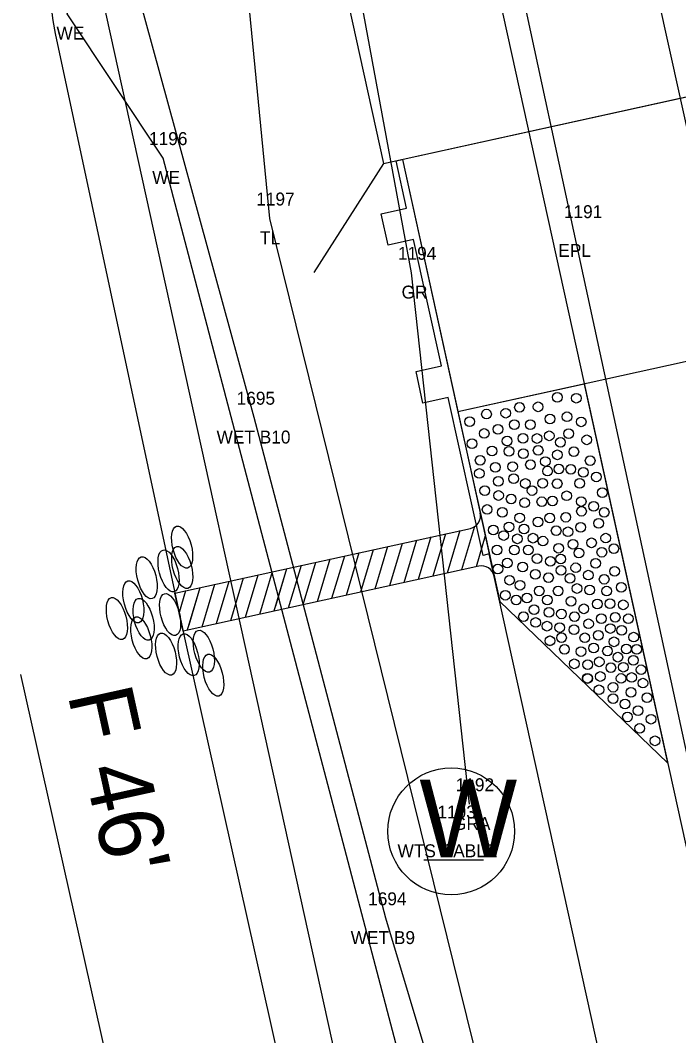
# Model space of a CAD drawing. Extents: x 2520975 to 2526538, y 881018 to 888064.
# Drawn here: x 2523752.6 to 2523803.6, y 884983.7 to 885062.2 of the extents above; entities that cross this region are included whole.
import ezdxf

# ---------------------------------------------------------------- set-up
doc = ezdxf.new("R2010")
doc.units = 0
for name, color, linetype in [('RD_EV_JurisArea', 7, 'Continuous'), ('RD_EX_GuardRail', 7, 'Continuous'), ('RD_EX_GuardRail_txCode', 7, 'Continuous'), ('RD_EX_H2O', 7, 'Continuous'), ('RD_EX_H2O_txCode', 7, 'Continuous'), ('RD_EX_H2O_WetLd_txCode', 7, 'Continuous'), ('RD_EX_Road', 7, 'Continuous'), ('RD_EX_Road_txCode', 7, 'Continuous'), ('RD_EX_UT', 7, 'Continuous'), ('RD_EX_UT_txCode', 7, 'Continuous'), ('RD_EX_VEG', 7, 'Continuous'), ('RD_EX_VEG_txCode', 7, 'Continuous'), ('RD_HC_Cl', 7, 'Continuous'), ('RD_PD_Bridge', 7, 'Continuous'), ('RD_PD_CstnLmt', 7, 'Continuous'), ('RD_PD_DR_ErosCtrl', 7, 'Continuous'), ('RD_PD_Final_TrvlWay', 7, 'Continuous'), ('RD_PD_GR', 7, 'Continuous'), ('RD_PD_PaveShd', 7, 'Continuous'), ('RD_SMD_Locator', 7, 'Continuous')]:
    doc.layers.add(name, color=color, linetype=linetype)

# ---------------------------------------------------------------- blocks, each defined once
blk = doc.blocks.new('TBC1')
at = {"layer": 'RD_PD_GR'}
blk.add_lwpolyline([(12.5, 2.5), (15, 2.5), (15, 0.492), (25, 0.492), (25, 2.5), (27.5, 2.5), (27.5, 0.492), (31.25, 0.492), (31.25, 0), (0, 0), (0, 0.492), (12.5, 0.492)], close=True, dxfattribs=at)

msp = doc.modelspace()

# ---------------------------------------------------------------- linework, layer by layer
at = {"layer": 'RD_EV_JurisArea'}
msp.add_lwpolyline([(2523827.748, 884469.643), (2523867.429, 884517.673), (2523885.95, 884534.838), (2523882.771, 884582.718), (2523847.739, 884736.424), (2523822.93, 884833.786), (2523804.257, 884914.891), (2523780.91, 884992.763), (2523770.735, 885031.476), (2523760.496, 885068.896)], dxfattribs=at)
at = {"layer": 'RD_EX_GuardRail'}
msp.add_lwpolyline([(2523787.377, 885001.584), (2523782.908, 885042.685), (2523776.151, 885079.302)], dxfattribs=at)
at = {"layer": 'RD_EX_H2O'}
msp.add_lwpolyline([(2523792.732, 884941.121), (2523763.674, 885051.555), (2523756.264, 885062.719), (2523770.471, 885094.548), (2523817.567, 885105.706), (2523827.825, 885105.996)], dxfattribs=at)
at = {"layer": 'RD_EX_Road'}
for p, q in [((2523795.465, 885045.906), (2523788.047, 885080.306)), ((2523816.996, 884946.299), (2523795.465, 885045.906))]:
    msp.add_line(p, q, dxfattribs=at)
at = {"layer": 'RD_EX_UT'}
msp.add_line((2523783.84, 884997.269), (2523788.469, 884997.269), dxfattribs=at)
msp.add_circle((2523785.968, 884999.477), 4.908, dxfattribs=at)
at = {"layer": 'RD_EX_VEG'}
msp.add_lwpolyline([(2523800.231, 884418.22), (2523892.245, 884498.974), (2523844.575, 884752.813), (2523771.945, 885046.883), (2523769.056, 885076.621)], dxfattribs=at)
at = {"layer": 'RD_HC_Cl'}
msp.add_line((2523641.165, 885794.201), (2524197.759, 883266.557), dxfattribs=at)
at = {"layer": 'RD_PD_Bridge'}
for p, q in [((2523780.729, 885051.128), (2523826.629, 885061.235)), ((2523780.729, 885051.128), (2523775.344, 885042.702)), ((2523782.194, 885051.45), (2523786.495, 885031.918)), ((2523829.465, 885041.381), (2523786.495, 885031.918))]:
    msp.add_line(p, q, dxfattribs=at)
for points in [[(2523752.772, 885178.086), (2523780.729, 885051.128)], [(2523780.729, 885051.128), (2523826.629, 885061.235)]]:
    msp.add_lwpolyline(points, dxfattribs=at)
at = {"layer": 'RD_PD_CstnLmt'}
for p, q in [((2523755.336, 885061.182), (2523765.326, 885014.455)), ((2523765.326, 885014.455), (2523787.173, 884916.87))]:
    msp.add_line(p, q, dxfattribs=at)
msp.add_arc((2523774.894, 885065.364), 20, 102.41848, 192.06773, dxfattribs=at)
at = {"layer": 'RD_PD_DR_ErosCtrl'}
msp.add_line((2523752.64, 885011.615), (2523774.487, 884914.03), dxfattribs=at)
msp.add_arc((2523774.894, 885065.364), 33, 102.41848, 192.06773, dxfattribs=at)
at = {"layer": 'RD_PD_Final_TrvlWay'}
for p, q in [((2523636.679, 885619.273), (2523984.702, 884038.805)), ((2523696.801, 885485.745), (2524014, 884045.256))]:
    msp.add_line(p, q, dxfattribs=at)
at = {"layer": 'RD_PD_GR'}
msp.add_line((2523896.44, 884532.63), (2523788.914, 885020.932), dxfattribs=at)
at = {"layer": 'RD_PD_PaveShd'}
for p, q in [((2523796.261, 885034.069), (2523786.495, 885031.918)), ((2523796.261, 885034.069), (2523802.712, 885004.771)), ((2523786.495, 885031.918), (2523788.43, 885023.129)), ((2523764.591, 885017.892), (2523787.453, 885022.914)), ((2523786.64, 885022.736), (2523785.656, 885019.448)), ((2523786.64, 885022.736), (2523785.656, 885019.448)), ((2523787.777, 885023.049), (2523786.773, 885019.693)), ((2523788.43, 885023.129), (2523789.076, 885020.199)), ((2523783.288, 885021.999), (2523782.304, 885018.712)), ((2523784.405, 885022.245), (2523783.421, 885018.957)), ((2523784.405, 885022.245), (2523783.421, 885018.957)), ((2523785.523, 885022.49), (2523784.539, 885019.203)), ((2523785.523, 885022.49), (2523784.539, 885019.203)), ((2523788.606, 885022.33), (2523787.89, 885019.939)), ((2523779.936, 885021.263), (2523778.952, 885017.975)), ((2523779.936, 885021.263), (2523778.952, 885017.975)), ((2523781.053, 885021.509), (2523780.069, 885018.221)), ((2523781.053, 885021.509), (2523780.069, 885018.221)), ((2523782.171, 885021.754), (2523781.187, 885018.466)), ((2523782.171, 885021.754), (2523781.187, 885018.466)), ((2523776.584, 885020.527), (2523775.6, 885017.239)), ((2523776.584, 885020.527), (2523775.6, 885017.239)), ((2523777.702, 885020.772), (2523776.718, 885017.485)), ((2523777.702, 885020.772), (2523776.718, 885017.485)), ((2523778.819, 885021.018), (2523777.835, 885017.73)), ((2523778.819, 885021.018), (2523777.835, 885017.73)), ((2523788.099, 885019.985), (2523765.218, 885014.959)), ((2523772.115, 885019.545), (2523771.131, 885016.258)), ((2523772.115, 885019.545), (2523771.131, 885016.258)), ((2523773.233, 885019.791), (2523772.249, 885016.503)), ((2523773.233, 885019.791), (2523772.37, 885016.908)), ((2523774.35, 885020.036), (2523773.366, 885016.748)), ((2523774.35, 885020.036), (2523773.366, 885016.748)), ((2523775.467, 885020.281), (2523774.483, 885016.994)), ((2523775.467, 885020.281), (2523774.483, 885016.994)), ((2523789.076, 885020.199), (2523789.721, 885017.269)), ((2523768.763, 885018.809), (2523767.779, 885015.521)), ((2523768.763, 885018.809), (2523767.779, 885015.521)), ((2523769.881, 885019.054), (2523768.897, 885015.767)), ((2523769.881, 885019.054), (2523768.897, 885015.767)), ((2523770.998, 885019.3), (2523770.014, 885016.012)), ((2523770.998, 885019.3), (2523770.014, 885016.012)), ((2523765.412, 885018.073), (2523764.91, 885016.398)), ((2523766.529, 885018.318), (2523765.545, 885015.03)), ((2523766.529, 885018.318), (2523765.666, 885015.436)), ((2523767.646, 885018.564), (2523766.662, 885015.276)), ((2523767.646, 885018.564), (2523766.662, 885015.276)), ((2523765.218, 885014.959), (2523764.591, 885017.892)), ((2523802.712, 885004.771), (2523789.721, 885017.269))]:
    msp.add_line(p, q, dxfattribs=at)
for centre in [(2523794.177, 885033.047), (2523794.177, 885033.047), (2523795.645, 885032.98), (2523795.645, 885032.98), (2523788.701, 885031.749), (2523788.701, 885031.749), (2523790.191, 885031.82), (2523790.191, 885031.82), (2523791.255, 885032.267), (2523791.255, 885032.267), (2523792.695, 885032.312), (2523792.695, 885032.312), (2523787.391, 885031.169), (2523787.391, 885031.169), (2523787.391, 885031.169), (2523790.857, 885030.939), (2523790.857, 885030.939), (2523792.098, 885030.94), (2523792.098, 885030.94), (2523793.614, 885031.376), (2523793.614, 885031.376), (2523794.925, 885031.542), (2523794.925, 885031.542), (2523796.028, 885031.15), (2523796.028, 885031.15), (2523788.522, 885030.252), (2523788.522, 885030.252), (2523789.59, 885030.574), (2523789.59, 885030.574), (2523795.053, 885030.242), (2523795.053, 885030.242), (2523787.581, 885029.458), (2523787.581, 885029.458), (2523790.297, 885029.666), (2523790.297, 885029.666), (2523791.529, 885029.869), (2523791.529, 885029.869), (2523792.61, 885029.863), (2523792.61, 885029.863), (2523793.554, 885030.07), (2523793.554, 885030.07), (2523794.424, 885029.569), (2523794.424, 885029.569), (2523796.459, 885029.76), (2523796.459, 885029.76), (2523789.128, 885028.892), (2523789.128, 885028.892), (2523790.445, 885028.871), (2523790.445, 885028.871), (2523791.55, 885028.688), (2523791.55, 885028.688), (2523792.699, 885028.941), (2523792.699, 885028.941), (2523794.188, 885028.599), (2523794.188, 885028.599), (2523795.46, 885028.839), (2523795.46, 885028.839), (2523788.21, 885028.175), (2523788.21, 885028.175), (2523792.104, 885027.837), (2523792.104, 885027.837), (2523793.26, 885028.082), (2523796.722, 885028.151), (2523796.722, 885028.151), (2523788.153, 885027.158), (2523788.153, 885027.158), (2523789.378, 885027.639), (2523789.378, 885027.639), (2523790.717, 885027.693), (2523790.717, 885027.693), (2523793.423, 885027.339), (2523793.423, 885027.339), (2523794.299, 885027.497), (2523794.299, 885027.497), (2523795.224, 885027.483), (2523795.224, 885027.483), (2523796.188, 885027.242), (2523796.188, 885027.242), (2523789.612, 885026.556), (2523789.612, 885026.556), (2523790.809, 885026.756), (2523790.809, 885026.756), (2523791.71, 885026.383), (2523791.71, 885026.383), (2523793.053, 885026.403), (2523793.053, 885026.403), (2523794.168, 885026.372), (2523794.168, 885026.372), (2523795.909, 885026.389), (2523795.909, 885026.389), (2523797.198, 885026.893), (2523797.198, 885026.893), (2523788.569, 885025.835), (2523788.569, 885025.835), (2523789.633, 885025.454), (2523789.633, 885025.454), (2523792.229, 885025.836), (2523792.229, 885025.836), (2523794.899, 885025.43), (2523794.899, 885025.43), (2523797.661, 885025.679), (2523797.661, 885025.679), (2523790.607, 885025.184), (2523790.607, 885025.184), (2523791.656, 885024.89), (2523791.656, 885024.89), (2523792.982, 885024.969), (2523792.982, 885024.969), (2523793.808, 885025.033), (2523793.808, 885025.033), (2523796.028, 885024.989), (2523796.028, 885024.989), (2523788.751, 885024.374), (2523788.751, 885024.374), (2523789.924, 885024.147), (2523789.924, 885024.147), (2523796.051, 885024.238), (2523796.051, 885024.238), (2523796.992, 885024.618), (2523796.992, 885024.618), (2523797.807, 885024.157), (2523791.266, 885023.725), (2523791.266, 885023.725), (2523792.68, 885023.406), (2523792.68, 885023.406), (2523793.598, 885023.71), (2523793.598, 885023.71), (2523794.837, 885023.774), (2523794.837, 885023.774), (2523797.383, 885023.302), (2523797.383, 885023.302), (2523789.226, 885022.785), (2523789.226, 885022.785), (2523790.029, 885022.359), (2523790.029, 885022.359), (2523790.438, 885023.028), (2523790.438, 885023.028), (2523791.609, 885022.864), (2523791.609, 885022.864), (2523794.092, 885022.736), (2523794.092, 885022.736), (2523795.002, 885022.647), (2523795.002, 885022.647), (2523795.989, 885022.995), (2523795.989, 885022.995), (2523791.09, 885022.103), (2523791.09, 885022.103), (2523792.304, 885022.154), (2523792.304, 885022.154), (2523793.064, 885021.927), (2523793.064, 885021.927), (2523795.39, 885021.686), (2523795.39, 885021.686), (2523796.828, 885021.793), (2523796.828, 885021.793), (2523797.929, 885022.157), (2523797.929, 885022.157), (2523789.509, 885021.243), (2523789.509, 885021.243), (2523790.85, 885021.234), (2523790.85, 885021.234), (2523791.928, 885021.243), (2523791.928, 885021.243), (2523794.284, 885021.376), (2523794.284, 885021.376), (2523795.849, 885021.011), (2523795.849, 885021.011), (2523797.624, 885021.069), (2523797.624, 885021.069), (2523798.556, 885021.349), (2523798.556, 885021.349), (2523790.304, 885020.24), (2523790.304, 885020.24), (2523791.492, 885019.926), (2523791.492, 885019.926), (2523792.616, 885020.572), (2523792.616, 885020.572), (2523793.648, 885020.356), (2523793.648, 885020.356), (2523794.447, 885020.541), (2523794.447, 885020.541), (2523797.14, 885020.211), (2523797.14, 885020.211), (2523789.581, 885019.774), (2523789.581, 885019.774), (2523792.478, 885019.352), (2523792.478, 885019.352), (2523794.474, 885019.665), (2523794.474, 885019.665), (2523795.609, 885019.863), (2523795.609, 885019.863), (2523796.576, 885019.295), (2523796.576, 885019.295), (2523798.61, 885019.596), (2523798.61, 885019.596), (2523790.483, 885018.905), (2523790.483, 885018.905), (2523791.298, 885018.516), (2523791.298, 885018.516), (2523793.498, 885019.099), (2523793.498, 885019.099), (2523795.158, 885019.047), (2523795.158, 885019.047), (2523797.805, 885018.979), (2523797.805, 885018.979), (2523799.125, 885018.346), (2523799.125, 885018.346), (2523790.156, 885017.741), (2523790.156, 885017.741), (2523790.156, 885017.741), (2523792.778, 885018.074), (2523792.778, 885018.074), (2523794.245, 885018.069), (2523794.245, 885018.069), (2523795.708, 885018.262), (2523795.708, 885018.262), (2523796.687, 885018.145), (2523796.687, 885018.145), (2523798.005, 885018.061), (2523798.005, 885018.061), (2523790.995, 885017.367), (2523790.995, 885017.367), (2523791.829, 885017.53), (2523791.829, 885017.53), (2523793.414, 885017.367), (2523793.414, 885017.367), (2523795.247, 885017.273), (2523795.247, 885017.273), (2523797.274, 885017.07), (2523797.274, 885017.07), (2523798.251, 885017.088), (2523798.251, 885017.088), (2523799.279, 885016.998), (2523799.279, 885016.998), (2523791.561, 885016.081), (2523791.561, 885016.081), (2523792.384, 885016.62), (2523792.384, 885016.62), (2523793.543, 885016.418), (2523793.543, 885016.418), (2523794.5, 885016.298), (2523794.5, 885016.298), (2523795.509, 885016.078), (2523795.509, 885016.078), (2523796.23, 885016.69), (2523796.23, 885016.69), (2523798.659, 885016.025), (2523798.659, 885016.025), (2523792.502, 885015.634), (2523792.502, 885015.634), (2523793.388, 885015.348), (2523793.388, 885015.348), (2523794.369, 885015.241), (2523794.369, 885015.241), (2523796.597, 885015.531), (2523796.597, 885015.531), (2523797.58, 885015.934), (2523797.58, 885015.934), (2523799.679, 885015.921), (2523799.679, 885015.921), (2523794.506, 885014.456), (2523794.506, 885014.456), (2523795.477, 885015.075), (2523795.477, 885015.075), (2523796.308, 885014.448), (2523796.308, 885014.448), (2523797.351, 885014.644), (2523797.351, 885014.644), (2523798.288, 885015.167), (2523798.288, 885015.167), (2523799.166, 885015.023), (2523799.166, 885015.023), (2523800.085, 885014.5), (2523800.085, 885014.5), (2523793.605, 885014.216), (2523793.616, 885014.214), (2523796.992, 885013.653), (2523796.992, 885013.653), (2523798.57, 885014.138), (2523798.57, 885014.138), (2523794.734, 885013.56), (2523794.734, 885013.56), (2523796.006, 885013.387), (2523796.006, 885013.387), (2523798.062, 885013.427), (2523798.062, 885013.427), (2523798.865, 885012.951), (2523798.865, 885012.951), (2523799.526, 885013.58), (2523799.526, 885013.58), (2523800.322, 885013.555), (2523800.322, 885013.555), (2523795.493, 885012.436), (2523795.493, 885012.436), (2523796.537, 885012.372), (2523796.537, 885012.372), (2523797.422, 885012.591), (2523797.422, 885012.591), (2523798.324, 885012.132), (2523798.324, 885012.132), (2523799.283, 885012.176), (2523799.283, 885012.176), (2523800.068, 885012.709), (2523800.068, 885012.709), (2523796.5, 885011.323), (2523796.524, 885011.299), (2523797.507, 885011.455), (2523797.507, 885011.455), (2523799.116, 885011.305), (2523799.116, 885011.305), (2523799.93, 885011.38), (2523799.93, 885011.38), (2523800.664, 885011.976), (2523800.664, 885011.976), (2523798.499, 885010.627), (2523798.499, 885010.627), (2523800.803, 885010.942), (2523800.803, 885010.942), (2523797.408, 885010.427), (2523797.408, 885010.427), (2523798.498, 885009.749), (2523799.88, 885010.226), (2523799.88, 885010.226), (2523801.117, 885009.82), (2523801.117, 885009.82), (2523799.421, 885009.323), (2523799.421, 885009.323), (2523799.609, 885008.334), (2523799.609, 885008.334), (2523800.425, 885008.81), (2523800.425, 885008.81), (2523801.434, 885008.154), (2523801.434, 885008.154), (2523800.546, 885007.439), (2523800.546, 885007.439), (2523801.736, 885006.481)]:
    msp.add_circle(centre, 0.375, dxfattribs=at)
for centre, start, end in [((2523787.239, 885023.891), 282.38886, 12.41848), ((2523788.314, 885019.008), 12.41848, 102.38886)]:
    msp.add_arc(centre, 1, start, end, dxfattribs=at)
for centre in [(2523765.147, 885021.461), (2523765.147, 885021.461), (2523764.099, 885019.623), (2523764.099, 885019.623), (2523765.154, 885019.888), (2523765.154, 885019.888), (2523762.41, 885019.094), (2523762.41, 885019.094), (2523761.376, 885017.232), (2523761.376, 885017.232), (2523764.219, 885016.245), (2523764.219, 885016.245), (2523760.099, 885015.939), (2523760.099, 885015.939), (2523762.17, 885015.878), (2523762.17, 885015.878), (2523761.988, 885014.444), (2523761.988, 885014.444), (2523763.908, 885013.188), (2523763.908, 885013.188), (2523765.652, 885013.142), (2523765.652, 885013.142), (2523766.828, 885013.409), (2523767.556, 885011.56)]:
    msp.add_ellipse(centre, major_axis=(0.426, -1.616), ratio=0.429445, dxfattribs=at)
at = {"layer": 'RD_SMD_Locator'}
for centre in [(2523763.674, 885051.555), (2523771.945, 885046.883), (2523795.465, 885045.906), (2523782.908, 885042.685), (2523770.735, 885031.476), (2523775.333, 885013.358), (2523787.377, 885001.584), (2523780.91, 884992.763)]:
    msp.add_circle(centre, 0.001, dxfattribs=at)

# ---------------------------------------------------------------- block references
at = {"layer": 'RD_PD_Bridge', "rotation": 102.41848259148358}
msp.add_blockref('TBC1', (2523788.914, 885020.932), dxfattribs=at)

# ---------------------------------------------------------------- texts
at = {"layer": 'RD_EX_GuardRail_txCode'}
for s, p in [('1194', (2523781.845, 885043.685)), ('GR', (2523782.129, 885040.685)), ('1192', (2523786.314, 885002.584)), ('GRA', (2523786.109, 884999.584))]:
    msp.add_text(s, height=1, dxfattribs=at).set_placement(p)
at = {"layer": 'RD_EX_H2O_txCode'}
for s, p in [('WE', (2523755.425, 885060.719)), ('1196', (2523762.587, 885052.555)), ('WE', (2523762.835, 885049.555))]:
    msp.add_text(s, height=1, dxfattribs=at).set_placement(p)
at = {"layer": 'RD_EX_H2O_WetLd_txCode'}
for s, p in [('1695', (2523769.365, 885032.476)), ('WET B10', (2523767.813, 885029.476)), ('1694', (2523779.54, 884993.763)), ('WET B9', (2523778.193, 884990.763))]:
    msp.add_text(s, height=1, dxfattribs=at).set_placement(p)
at = {"layer": 'RD_EX_Road_txCode'}
for s, p in [('1191', (2523794.686, 885046.906)), ('EPL', (2523794.261, 885043.906))]:
    msp.add_text(s, height=1, dxfattribs=at).set_placement(p)
at = {"layer": 'RD_EX_UT'}
msp.add_text('W', height=6, dxfattribs=at).set_placement((2523783.504, 884997.476))
at = {"layer": 'RD_EX_UT_txCode'}
for s, p in [('1193', (2523784.905, 885000.477)), ('WTS CABLE', (2523781.815, 884997.477))]:
    msp.add_text(s, height=1, dxfattribs=at).set_placement(p)
at = {"layer": 'RD_EX_VEG_txCode'}
for s, p in [('1197', (2523770.882, 885047.883)), ('TL', (2523771.173, 885044.883))]:
    msp.add_text(s, height=1, dxfattribs=at).set_placement(p)
at = {"layer": 'RD_PD_CstnLmt'}
msp.add_text("F 46'", height=5, rotation=282.41848, dxfattribs=at).set_placement((2523756.274, 885010.084))

doc.saveas('drawing.dxf')
